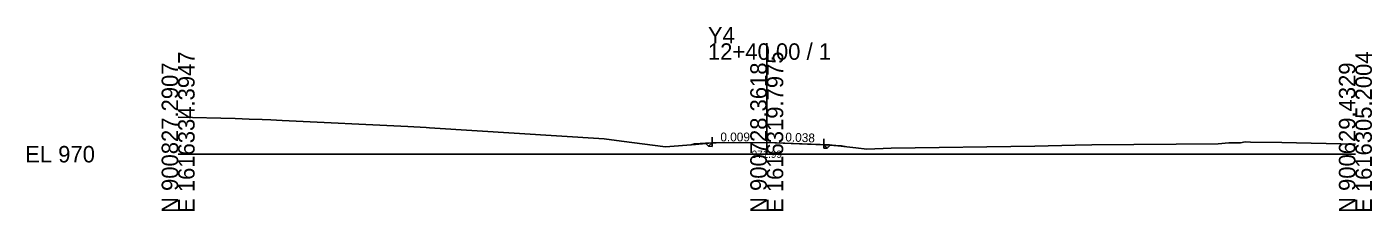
# Model space of a CAD drawing. Extents: x -26 to 2603, y -10 to 522.
# Drawn here: x -25.7 to 202.8, y -9.7 to 21.7 of the extents above; entities that cross this region are included whole.
import ezdxf

# ---------------------------------------------------------------- set-up
doc = ezdxf.new("R2010")
doc.units = 0
for name, color, linetype in [('Exist Cross Section Cell', 7, 'Continuous'), ('Exist XS Center Line Elevation Label', 7, 'Continuous'), ('Exist XS Ground Line', 7, 'Continuous'), ('Prop XS Dump Level', 7, 'Continuous'), ('Prop XS Earthwork Shape', 7, 'Continuous'), ('Prop XS EOT Tick Mark', 7, 'Continuous'), ('Prop XS Finish Grade', 7, 'Continuous'), ('Prop XS Finish Grade Earthwork', 7, 'Continuous'), ('Prop XS Finish Grade Pavement', 7, 'Continuous'), ('Prop XS Pvmt Edge Slope', 7, 'Continuous'), ('Prop XS SE Text', 7, 'Continuous'), ('Prop XS Subgrade Earthwork', 7, 'Continuous')]:
    doc.layers.add(name, color=color, linetype=linetype)

msp = doc.modelspace()

# ---------------------------------------------------------------- linework, layer by layer
at = {"layer": 'Exist Cross Section Cell'}
for p, q in [((100, 0), (100, 18.87)), ((0, 0), (100, 0)), ((100, 0), (200, 0))]:
    msp.add_line(p, q, dxfattribs=at)
at = {"layer": 'Exist XS Ground Line'}
for p, q in [((0, 6.29), (9.71, 6.06)), ((9.71, 6.06), (12.08, 5.97)), ((12.08, 5.97), (14.26, 5.88)), ((14.26, 5.88), (15.73, 5.83)), ((15.73, 5.83), (17.7, 5.75)), ((17.7, 5.75), (39.02, 4.69)), ((39.02, 4.69), (42.15, 4.52)), ((42.15, 4.52), (42.7, 4.49)), ((42.7, 4.49), (72.38, 2.59)), ((72.38, 2.59), (75.32, 2.22)), ((75.32, 2.22), (82.78, 1.23)), ((82.78, 1.23), (87.92, 1.67)), ((87.92, 1.67), (90.71, 1.92)), ((90.71, 1.92), (91.4, 1.92)), ((91.4, 1.92), (100.23, 1.99)), ((100.23, 1.99), (104.51, 1.83)), ((104.51, 1.83), (110.58, 1.58)), ((110.58, 1.58), (115.16, 1.09)), ((115.16, 1.09), (116.98, 0.88)), ((116.98, 0.88), (121.16, 1.03)), ((121.16, 1.03), (145.52, 1.38)), ((145.52, 1.38), (152.4, 1.53)), ((152.4, 1.53), (155.24, 1.58)), ((155.24, 1.58), (176.68, 1.75)), ((176.68, 1.75), (178.51, 1.91)), ((178.51, 1.91), (180.51, 1.96)), ((180.51, 1.96), (181.25, 2.09)), ((181.25, 2.09), (182.2, 2.06)), ((182.2, 2.06), (187.5, 2)), ((187.5, 2), (200, 1.69))]:
    msp.add_line(p, q, dxfattribs=at)
at = {"layer": 'Prop XS Dump Level'}
for p, q in [((100, 1.99), (90.62, 1.91)), ((109.68, 1.62), (100, 1.99))]:
    msp.add_line(p, q, dxfattribs=at)
at = {"layer": 'Prop XS Earthwork Shape'}
for points in [[(87.18, 1.61), (87.92, 1.67), (89.64, 1.82), (89.61, 1.85), (87.71, 1.74)], [(89.64, 1.82), (90.71, 1.92), (90.13, 1.34)], [(90.71, 1.33), (90.71, 1.92), (90.13, 1.34)], [(109.68, 1.04), (109.68, 1.62), (110.26, 1.04)], [(109.68, 1.62), (110.78, 1.56), (110.26, 1.04)], [(109.68, 1.62), (110.58, 1.58), (110.78, 1.56)], [(110.78, 1.56), (113.32, 1.29), (112.68, 1.45)]]:
    msp.add_lwpolyline(points, close=True, dxfattribs=at)
at = {"layer": 'Prop XS EOT Tick Mark'}
for p, q in [((90.71, 1.92), (90.71, 2.92)), ((109.68, 1.62), (109.68, 2.62))]:
    msp.add_line(p, q, dxfattribs=at)
at = {"layer": 'Prop XS Finish Grade'}
for p, q in [((90.71, 1.92), (89.61, 1.85)), ((109.68, 1.62), (110.78, 1.56))]:
    msp.add_line(p, q, dxfattribs=at)
at = {"layer": 'Prop XS Finish Grade Earthwork'}
for p, q in [((87.71, 1.74), (87.18, 1.61)), ((89.61, 1.85), (87.71, 1.74)), ((110.78, 1.56), (112.68, 1.45)), ((112.68, 1.45), (113.33, 1.29))]:
    msp.add_line(p, q, dxfattribs=at)
at = {"layer": 'Prop XS Finish Grade Pavement'}
for p, q in [((90.71, 1.92), (100, 1.99)), ((100, 1.99), (109.68, 1.62))]:
    msp.add_line(p, q, dxfattribs=at)
at = {"layer": 'Prop XS Pvmt Edge Slope'}
for p, q in [((90.71, 1.92), (90.13, 1.34)), ((109.68, 1.62), (110.26, 1.04))]:
    msp.add_line(p, q, dxfattribs=at)
at = {"layer": 'Prop XS Subgrade Earthwork'}
for p, q in [((90.13, 1.34), (89.61, 1.85)), ((90.71, 1.33), (90.13, 1.34)), ((90.71, 1.33), (90.71, 1.92)), ((109.68, 1.04), (109.68, 1.62)), ((109.68, 1.04), (110.26, 1.04)), ((110.26, 1.04), (110.78, 1.56))]:
    msp.add_line(p, q, dxfattribs=at)

# ---------------------------------------------------------------- texts
at = {"layer": 'Exist Cross Section Cell'}
for s, p in [('Y4', (90, 18.87)), ('12+40.00 / 1', (90, 16.07)), ('EL 970', (-26, -1.4))]:
    msp.add_text(s, height=2.8, dxfattribs=at).set_placement(p)
for s, p in [('E 1616334.3947', (2.8, -10)), ('E 1616319.7975', (102.8, -10)), ('E 1616305.2004', (202.8, -10)), ('N 900827.2907', (0, -10)), ('N 900728.3618', (100, -10)), ('N 900629.4329', (200, -10))]:
    msp.add_text(s, height=2.8, rotation=90, dxfattribs=at).set_placement(p)
at = {"layer": 'Exist XS Center Line Elevation Label'}
msp.add_text('971.99', height=1.25, dxfattribs=at).set_placement((97.45, -0.63))
at = {"layer": 'Prop XS Dump Level'}
msp.add_text('Eop', height=0.3, dxfattribs=at).set_placement((109.68, 1.32))
at = {"layer": 'Prop XS SE Text'}
for s, rotation, p in [('0.009', 359.9916, (92.12, 2.18)), ('0.038', 357.7874, (103.13, 2.19))]:
    msp.add_text(s, height=1.5, rotation=rotation, dxfattribs=at).set_placement(p)

doc.saveas('drawing.dxf')
